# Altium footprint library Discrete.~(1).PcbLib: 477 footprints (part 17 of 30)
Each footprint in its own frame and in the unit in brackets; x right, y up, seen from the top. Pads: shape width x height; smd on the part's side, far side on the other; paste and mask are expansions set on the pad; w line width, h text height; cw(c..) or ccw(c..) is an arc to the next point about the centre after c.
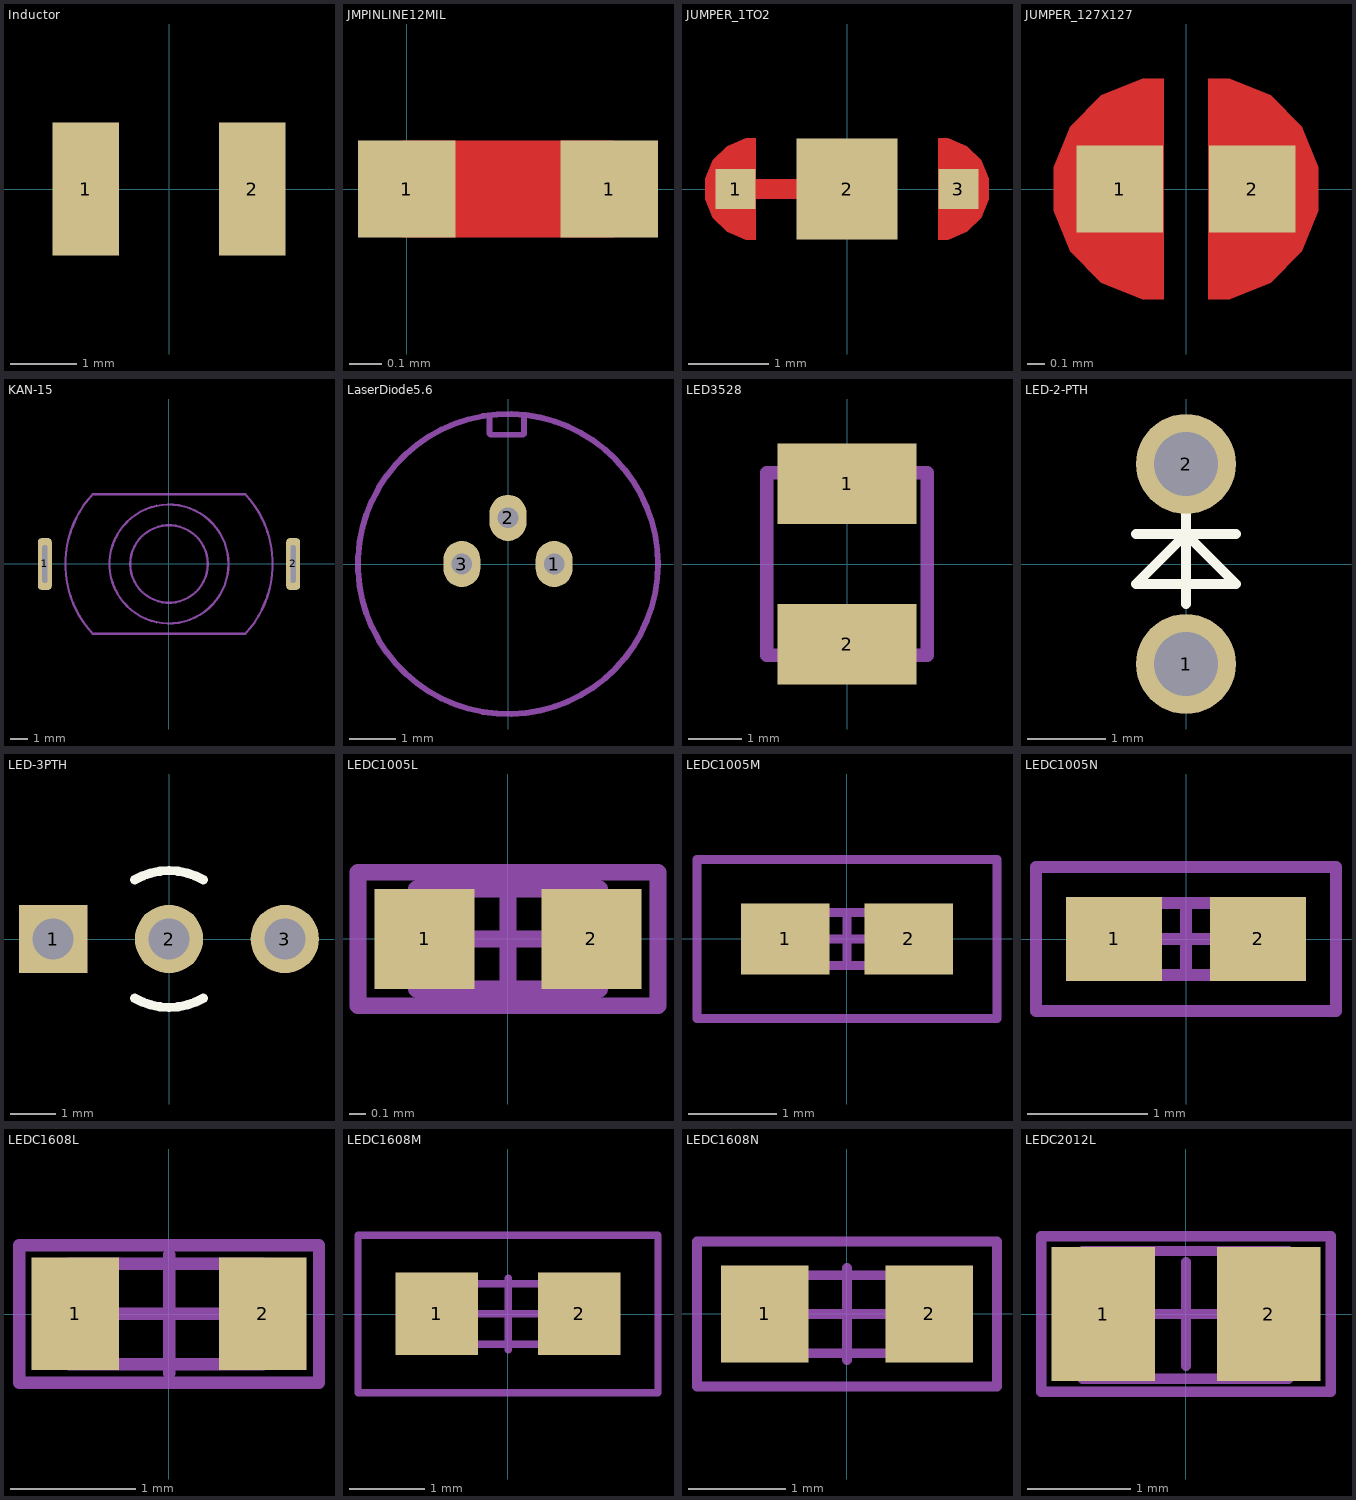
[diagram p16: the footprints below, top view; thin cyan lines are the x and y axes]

## Inductor [mm]
pads (2):
  rect 1x2 smd: 1(-1.25,0) 2(1.25,0)

## JMPINLINE12MIL [mil]
pads (2):
  rect 12x12 smd: 1(0,0) 1(25,0)
Top Layer:
  lines w12: 0,0 25,0

## JUMPER_1TO2 [mm] "1mmX1mm Jumper"
pads (3):
  rect 0.5x0.5 smd: 1(-1.397,0) 3(1.397,0)
  rect 1.27x1.27 smd: 2(0,0)
Top Layer:
  region: -1.143,0.635 -1.269,0.635 -1.503,0.538 -1.681,0.36 -1.778,0.126 -1.778,-0.126 -1.681,-0.36 -1.503,-0.538 -1.269,-0.635 -1.143,-0.635
  region: 1.143,-0.635 1.269,-0.635 1.503,-0.538 1.681,-0.36 1.778,-0.126 1.778,0.126 1.681,0.36 1.503,0.538 1.269,0.635 1.143,0.635
  lines w0.254: -1.397,0 0,0
Top Solder:
  region: -1.041,0.737 -1.143,0.737 -1.24,0.737 -1.427,0.686 -1.595,0.589 -1.732,0.452 -1.829,0.284 -1.88,0.097 -1.88,-0.097 -1.829,-0.284 -1.732,-0.452 -1.595,-0.589 -1.427,-0.686 -1.24,-0.737 -1.143,-0.737 -1.041,-0.737
  region: 1.041,-0.737 1.143,-0.737 1.24,-0.737 1.427,-0.686 1.595,-0.589 1.732,-0.452 1.829,-0.284 1.88,-0.097 1.88,0.097 1.829,0.284 1.732,0.452 1.595,0.589 1.427,0.686 1.24,0.737 1.143,0.737 1.041,0.737

## JUMPER_127X127 [mm] "1mmX1mm Jumper"
pads (2):
  rect 0.5x0.5 smd: 1(-0.381,0) 2(0.381,0)
Top Layer:
  region: 0.127,-0.635 0.253,-0.635 0.487,-0.538 0.665,-0.36 0.762,-0.126 0.762,0.126 0.665,0.36 0.487,0.538 0.253,0.635 0.127,0.635
  region: -0.127,0.635 -0.253,0.635 -0.487,0.538 -0.665,0.36 -0.762,0.126 -0.762,-0.126 -0.665,-0.36 -0.487,-0.538 -0.253,-0.635 -0.127,-0.635
Top Solder:
  region: 0.025,-0.737 0.127,-0.737 0.224,-0.737 0.411,-0.686 0.579,-0.589 0.716,-0.452 0.813,-0.284 0.864,-0.097 0.864,0.097 0.813,0.284 0.716,0.452 0.579,0.589 0.411,0.686 0.224,0.737 0.127,0.737 0.025,0.737
  region: -0.025,0.737 -0.127,0.737 -0.224,0.737 -0.411,0.686 -0.579,0.589 -0.716,0.452 -0.813,0.284 -0.864,0.097 -0.864,-0.097 -0.813,-0.284 -0.716,-0.452 -0.579,-0.589 -0.411,-0.686 -0.224,-0.737 -0.127,-0.737 -0.025,-0.737

## KAN-15 [mm]
pads (2):
  rrect50% 0.8x3 hole 0.3 slot 2.2 at 90 deg: 1(-7.2,0) 2(7.2,0)
Mechanical 13:
  circle w0.127: c0,0 r2.25
  circle w0.127: c0,0 r3.45
  lines w0.127: -4.428,-4.053 cw(c0,0) -4.424,4.057 ; -4.425,-4.05 4.424,-4.05 ; -4.424,4.05 4.424,4.05 ; 4.424,-4.057 ccw(c0,0) 4.427,4.053
3D body: height 8.1, standoff 0, extent -2.249,-2.249 2.249,2.249
3D body: height 6.1, standoff 0, extent -3.449,-3.449 3.449,3.449
3D body: height 4.1, standoff 0, extent -6.066,-4.12 6.066,4.12

## LaserDiode5.6 [mm]
height 17
pads (3):
  oval 0.8x1 hole 0.45: 1(1,0) 2(0,1) 3(-1,0)
Mechanical 13:
  circle w0.127: c0,0 r3.25
  lines w0.127: -0.4,3.2 -0.4,2.825 -0.375,2.8 0.325,2.8 0.35,2.825 0.35,3.225

## LED3528 [mm]
pads (2):
  rect 2.6x1.5 smd: 1(0,1.5) 2(0,-1.5)
Mechanical 13:
  lines w0.254: -1.5,-1.7 -1.5,1.7 1.5,1.7 1.5,-1.7 -1.5,-1.7
3D body: height 2.1, standoff 0, extent -1.5,-1.7 1.5,1.7

## LED-2-PTH [mil]
pads (2):
  round 50 hole 32: 1(0,-50) 2(0,50)
Top Overlay:
  lines w5: -25,15 25,15 ; 0,-20 0,25 ; 0,-10 0,15 ; 0,15 25,-10 -25,-10 0,15

## LED-3PTH [mm]
pads (3):
  rect 1.5x1.5 hole 0.9: 1(-2.54,0)
  round 1.5 hole 0.9: 2(0,0) 3(2.54,0)
Top Overlay:
  lines w0.2: -0.75,-1.299 ccw(c0,0) 0.75,-1.299 ; -0.75,1.299 cw(c0,0) 0.75,1.299

## LEDC1005L [mm] "Chip LED, Body 1.1x0.5mm, IPC High Density"
height 0.4
pads (2):
  rect 0.6x0.6 smd: 1(-0.5,0) 2(0.5,0)
Mechanical 13:
  lines w0.1: -0.55,-0.3 -0.55,0.3 0.55,0.3 0.55,-0.3 -0.55,-0.3
Mechanical 15:
  lines w0.1: -0.3,0 0.3,0 ; 0,-0.3 0,0.3 ; -0.9,-0.4 -0.9,0.4 0.9,0.4 0.9,-0.4 -0.9,-0.4
3D body "ChipLedWith-Yellow.stp": height 0.16, standoff 0, extent -0.502,-0.252 0.502,0.252

## LEDC1005M [mm] "Chip LED, Body 1.1x0.5mm, IPC Low Density"
height 0.4
pads (2):
  rect 1x0.8 smd: 1(-0.7,0) 2(0.7,0)
Mechanical 13:
  lines w0.1: -0.55,-0.3 -0.55,0.3 0.55,0.3 0.55,-0.3 -0.55,-0.3
Mechanical 15:
  lines w0.1: -0.3,0 0.3,0 ; 0,-0.3 0,0.3 ; -1.7,-0.9 -1.7,0.9 1.7,0.9 1.7,-0.9 -1.7,-0.9
3D body "ChipLedWith-Yellow.stp": height 0.16, standoff 0, extent -0.502,-0.252 0.502,0.252

## LEDC1005N [mm] "Chip LED,  Body 1.1x0.5mm, IPC Medium Density"
height 0.4
pads (2):
  rect 0.8x0.7 smd: 1(-0.6,0) 2(0.6,0)
Mechanical 13:
  lines w0.1: -0.55,-0.3 0.55,-0.3 0.55,0.3 -0.55,0.3 -0.55,-0.3
Mechanical 15:
  lines w0.1: -0.3,0 0.3,0 ; 0,-0.3 0,0.3 ; -1.25,-0.6 1.25,-0.6 1.25,0.6 -1.25,0.6 -1.25,-0.6
3D body "ChipLedWith-Yellow.stp": height 0.16, standoff 0, extent -0.502,-0.252 0.502,0.252

## LEDC1608L [mm] "Chip LED, Body 1.6x0.8mm, IPC High Density"
height 0.6
pads (2):
  rect 0.7x0.9 smd: 1(-0.75,0) 2(0.75,0)
Mechanical 13:
  lines w0.1: -0.8,-0.401 -0.261,-0.401 0.261,-0.401 0.75,-0.401 0.75,0.401 -0.8,0.401 -0.8,-0.401
Mechanical 15:
  lines w0.1: -0.475,0 0.475,0 ; 0,-0.475 0,0.475 ; -1.2,-0.55 -1.2,0.55 1.2,0.55 1.2,-0.55 -1.2,-0.55
3D body "LED 0603-W.STEP": height 0.47, standoff 0, extent -0.8,-0.401 0.8,0.401
3D body "LED 0603玻璃罩.STEP": height 0.61, standoff 0.21, extent -0.599,-0.401 0.599,0.401

## LEDC1608M [mm] "Chip LED, Body 1.6x0.8mm, IPC Low Density"
height 0.6
pads (2):
  rect 1.1x1.1 smd: 1(-0.95,0) 2(0.95,0)
Mechanical 13:
  lines w0.1: -0.8,-0.406 0.8,-0.406 0.8,0.406 -0.8,0.406 -0.8,-0.406
Mechanical 15:
  lines w0.1: -0.475,0 0.475,0 ; 0,-0.475 0,0.475 ; -2,-1.05 -2,1.05 2,1.05 2,-1.05 -2,-1.05
3D body "LED 0603-W.STEP": height 0.47, standoff 0, extent -0.8,-0.401 0.8,0.401
3D body "LED 0603玻璃罩.STEP": height 0.61, standoff 0.21, extent -0.599,-0.401 0.599,0.401

## LEDC1608N [mm] "Chip LED, Body 1.6x0.8mm, IPC Medium Density"
height 0.6
pads (2):
  rect 0.9x1 smd: 1(-0.85,0) 2(0.85,0)
Mechanical 13:
  lines w0.1: -0.813,-0.406 -0.813,0.401 0.8,0.401 0.8,-0.406 -0.813,-0.406
Mechanical 15:
  lines w0.1: -0.475,0 0.475,0 ; 0,-0.475 0,0.475 ; -1.55,-0.75 -1.55,0.75 1.55,0.75 1.55,-0.75 -1.55,-0.75
3D body "LED 0603玻璃罩.STEP": height 0.61, standoff 0.21, extent -0.599,-0.401 0.599,0.401
3D body "LED 0603-W.STEP": height 0.47, standoff 0, extent -0.8,-0.401 0.8,0.401

## LEDC2012L [mm] "Chip LED, Body 2.0x1.3mm, IPC High Density"
height 0.65
pads (2):
  rect 1x1.3 smd: 1(-0.8,0) 2(0.8,0)
Mechanical 13:
  lines w0.1: -1,-0.626 0.991,-0.626 0.991,0.61 -1,0.61 -1,-0.626
Mechanical 15:
  lines w0.1: -0.5,0 0.5,0 ; 0,-0.5 0,0.5 ; -1.4,-0.75 1.4,-0.75 1.4,0.75 -1.4,0.75 -1.4,-0.75
3D body "LED 0805-W.STEP": height 0.67, standoff 0, extent -1,-0.626 1,0.626
3D body "LED 0805玻璃罩.STEP": height 0.8, standoff 0.31, extent -0.749,-0.626 0.749,0.626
